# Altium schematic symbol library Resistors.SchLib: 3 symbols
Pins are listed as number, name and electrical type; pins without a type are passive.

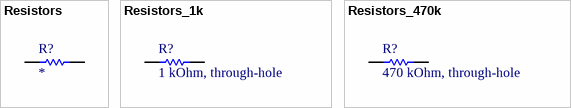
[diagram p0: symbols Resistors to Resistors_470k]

## Resistors
designator R?
Resistor
footprint RES_THRU_HOLE
pins: 1, 2

## Resistors_1k
designator R?, comment 1 kOhm, through-hole
Resistor
footprint RES_THRU_HOLE
pins: 1, 2

## Resistors_470k
designator R?, comment 470 kOhm, through-hole
Resistor
footprint RES_THRU_HOLE
pins: 1, 2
